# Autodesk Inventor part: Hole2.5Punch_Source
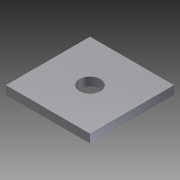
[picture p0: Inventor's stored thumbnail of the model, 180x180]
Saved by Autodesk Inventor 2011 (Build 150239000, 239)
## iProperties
Created: 2007-02
Part Number: Hole2.5Punch_Source
Material: Default
Document SubType Name: Sheet Metal
Designer: Autodesk, Inc.
Mass: 0.0950913 g
Surface Area: 2.38037 cm^2
Volume: 0.0950913 cm^3
Density: 1 g/cm^3
Sheet Metal Rule: 1 mm
Author: Autodesk, Inc.
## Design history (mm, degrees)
node "Face1"
  sketch "Sketch1"
    geometry: L1 (-5, 5)-(5, 5); L2 (5, 5)-(5, -5); L3 (5, -5)-(-5, -5); L4 (-5, -5)-(-5, 5); L5 (-5, 5)-(5, -5); 2 further points
    constraints: 10 end point, 2 parallel, 1 coincident, 1 horizontal, 1 midpoint, 1 perpendicular
    dimensions: "d0" = 10 distance of L2.end L3.end; "d1" = 10 distance of L1.end L2.end (= d0)
sketch "Sketch2"
  geometry: C1 r 1.25 at (0, 0); 2 further points
  constraints: 2 coincident, 1 centre point
  dimensions: "d3" = 2.5 diameter of C1
cut "Cut1" sketch "Sketch2" dims "d4" = 1 (= Thickness), "d5" = 0
body "Solid1"
face "Plate1" dims "Thickness" = 1
other parameters: "BendRadius" = 0.5, "BendReliefWidth" = 1 (= Thickness), "BendReliefDepth" = 0.5 (= 0.5 x Thickness), "CornerReliefSize" = 4 (= 4 x Thickness), "SeamGap" = 0.01, "MinimumRemnant" = 2 (= 2 x Thickness), "TransitionRadius" = 0.5 (= BendRadius), "JacobiRadiusSize" = 1 (= Thickness), "d2" = 0.5 (= BendRadius), "GapSize" = 1 (= Thickness)
